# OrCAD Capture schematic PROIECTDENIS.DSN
size A
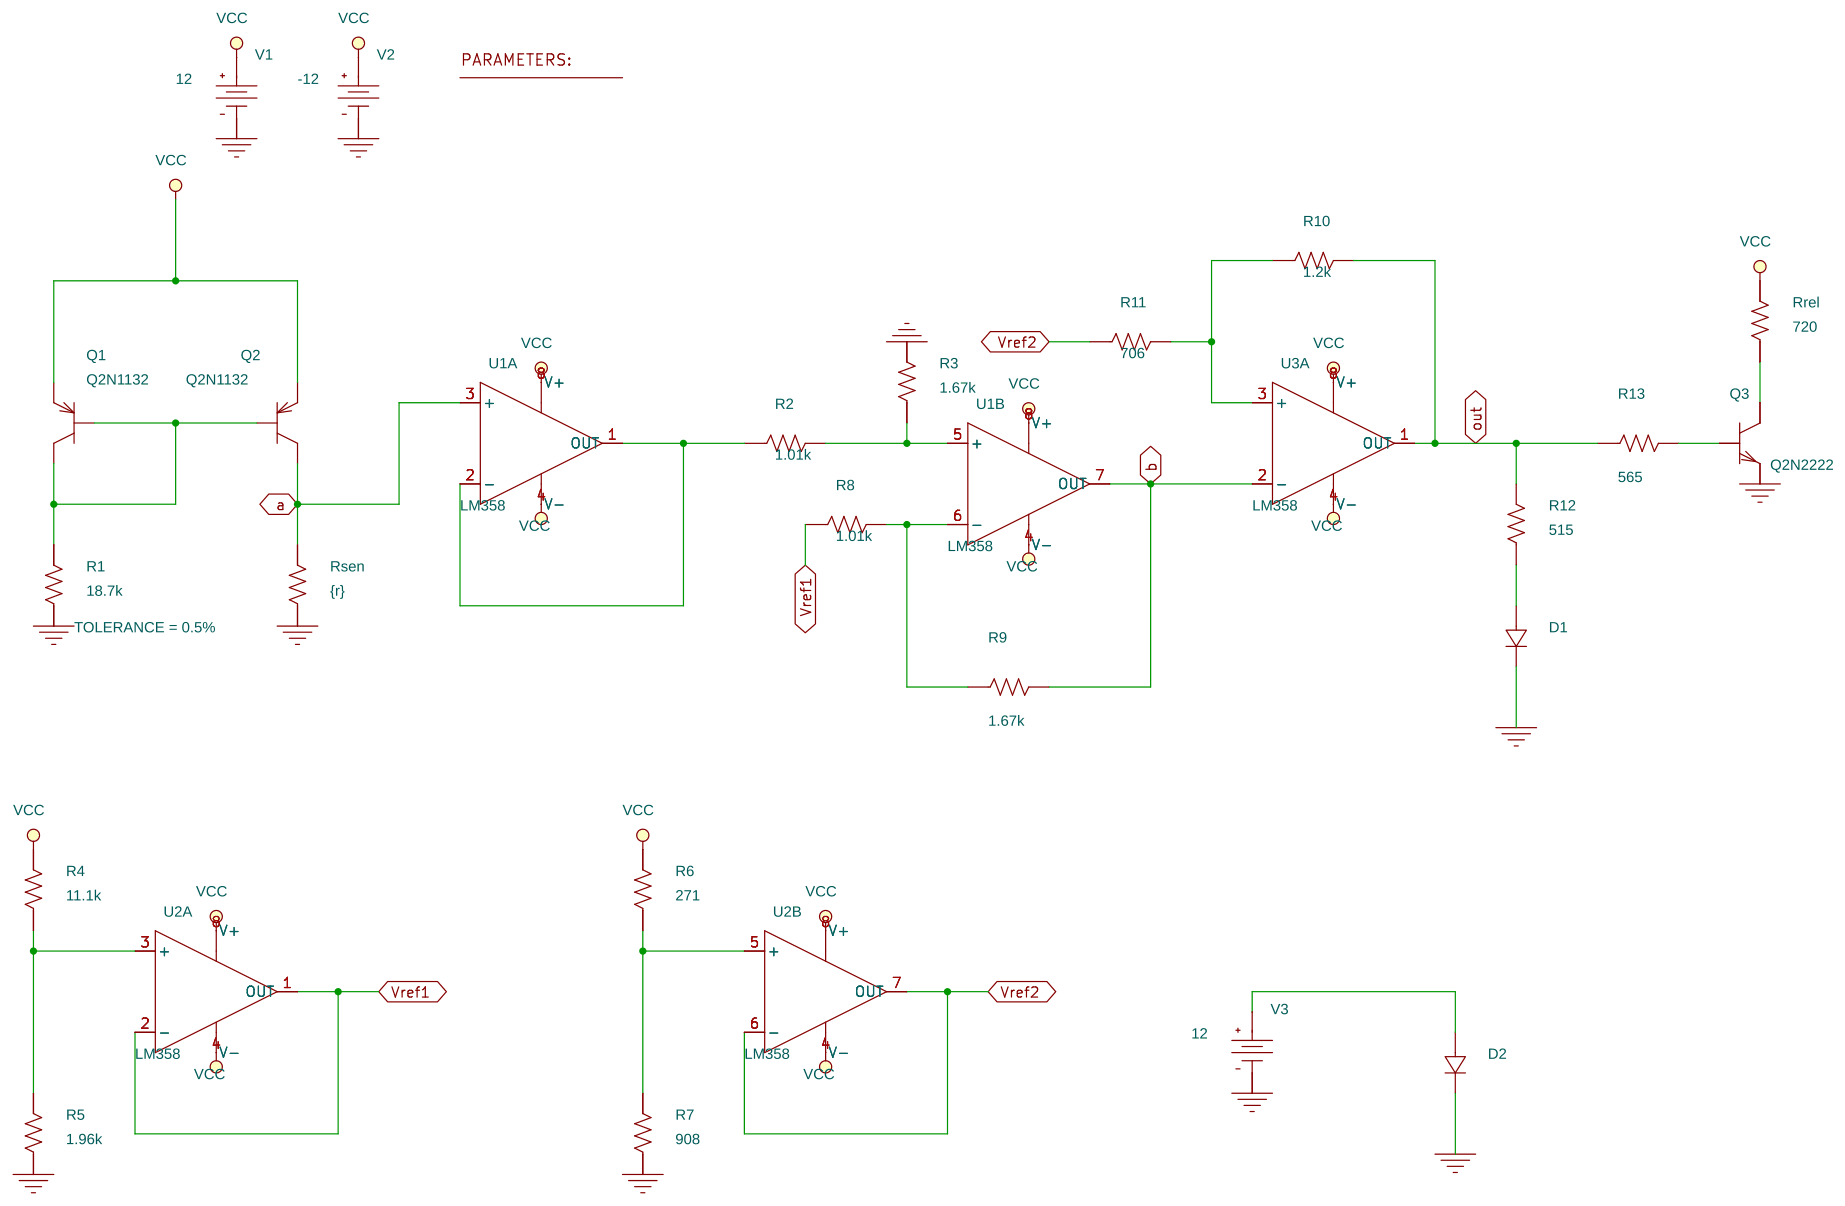
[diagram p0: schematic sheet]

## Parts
1  PARAM
D1  Dbreak
D2  Dbreak
Q1  Q2N1132  [TO5]
Q2  Q2N1132  [TO5]
Q3  Q2N2222  [TO18]
R1  18.7k  [AX/RC05]
R2  1.01k  [AX/RC05]
R3  1.67k  [AX/RC05]
R4  11.1k  [AX/RC05]
R5  1.96k  [AX/RC05]
R6  271  [AX/RC05]
R7  908  [AX/RC05]
R8  1.01k  [AX/RC05]
R9  1.67k  [AX/RC05]
R10  1.2k  [AX/RC05]
R11  706  [AX/RC05]
R12  515  [AX/RC05]
R13  565  [AX/RC05]
Rrel  720  [AX/RC05]
Rsen  {r}  [AX/RC05]
U1  LM358  [DIP.100/8/W.300/L.450]  (sections A,B)
U2  LM358  [DIP.100/8/W.300/L.450]  (sections A,B)
U3  LM358  [DIP.100/8/W.300/L.450]  (section A)
V1  VDC
V2  VDC
V3  VDC

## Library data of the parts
1 = PARAM: r: 3k
D1 D2 = Dbreak
Q1 Q2 = Q2N1132
Q3 = Q2N2222
R1-R3 R8-R13 Rrel = R: TOLERANCE: 0.5%
R4-R7 Rsen = R
U1-U3 = LM358
V1 V3 = VDC: DC: 12
V2 = VDC: DC: -12

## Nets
-VCC: U1.4(V-) U2.4(V-) U3.4(V-) V2.0(+)
VCC: Q1.1(e) Q2.1(e) R4.2 R6.2 Rrel.2 U1.8(V+) U2.8(V+) U3.8(V+) V1.0(+)
0: D1.1(2) D2.1(2) Q3.1(e) R1.1 R3.2 R5.1 R7.1 Rsen.1 V1.1(-) V2.1(-) V3.1(-)
a: Q2.3(c) Rsen.2 U1.3(+)
b: R9.2 U1.7(OUT) U3.2(-)
out: R10.2 R12.2 R13.1 U3.1(OUT)
Vref1: R8.1 U2.1(OUT) U2.2(-)
Vref2: R11.1 U2.6(-) U2.7(OUT)
N00143: Q1.2(b) Q1.3(c) Q2.2(b) R1.2
N00635: R2.1 U1.1(OUT) U1.2(-)
N00657: R2.2 R3.1 U1.5(+)
N00788: R8.2 R9.1 U1.6(-)
N01129: R4.1 R5.2 U2.3(+)
N01437: R6.1 R7.2 U2.5(+)
N01834: R10.1 R11.2 U3.3(+)
N02068: Q3.2(b) R13.2
N02072: Q3.3(c) Rrel.1
N03564: D1.0(1) R12.1
N04796: D2.0(1) V3.0(+)
